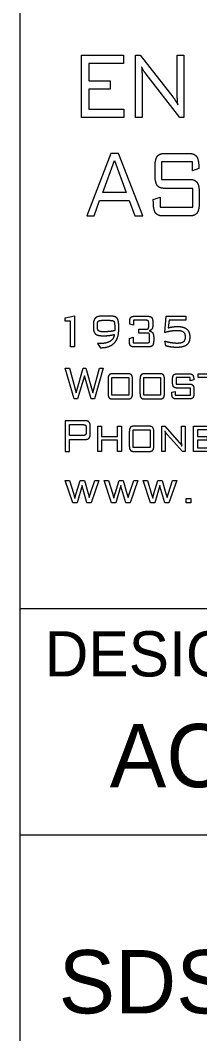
# Model space of a CAD drawing. Extents: x 0 to 34, y 0 to 22.
# Drawn here: x 32 to 32.397, y 2.06 to 4.301 of the extents above; entities that cross this region are included whole.
import ezdxf

# ---------------------------------------------------------------- set-up
doc = ezdxf.new("R2010")
doc.units = 0
for name, color, linetype in [('SH_Border', 7, 'Continuous'), ('SH_Data', 7, 'Continuous'), ('TX_X_20', 7, 'Continuous')]:
    doc.layers.add(name, color=color, linetype=linetype)

msp = doc.modelspace()

# ---------------------------------------------------------------- linework, layer by layer
at = {"layer": 'SH_Border'}
for p, q in [((32, 0.5), (32, 21.5)), ((32, 3), (33.5, 3)), ((32, 2.5), (33.5, 2.5))]:
    msp.add_line(p, q, dxfattribs=at)
at = {"layer": 'TX_X_20'}
for p, q in [((32.3205, 4.0065), (32.3719, 4.0065)), ((32.2979, 3.9618), (32.2979, 3.9738)), ((32.3958, 3.9164), (32.3958, 3.9009)), ((32.3733, 3.8681), (32.3169, 3.8681)), ((32.2009, 3.6465), (32.1793, 3.6465)), ((32.1811, 3.6374), (32.1977, 3.6374)), ((32.2536, 3.6465), (32.2812, 3.6465)), ((32.293, 3.6332), (32.293, 3.6271)), ((32.1618, 3.6299), (32.1618, 3.6208)), ((32.1705, 3.6225), (32.1705, 3.6269)), ((32.2087, 3.6145), (32.2087, 3.6145)), ((32.2177, 3.6166), (32.2177, 3.6256)), ((32.2841, 3.6257), (32.2841, 3.6297)), ((32.1708, 3.5861), (32.1763, 3.5771)), ((32.2861, 3.5939), (32.2861, 3.603)), ((32.295, 3.6002), (32.295, 3.5931)), ((32.3221, 3.5807), (32.3195, 3.5916)), ((32.2825, 3.5785), (32.2528, 3.5785)), ((32.2373, 3.5193), (32.205, 3.5193)), ((32.3079, 3.5193), (32.2756, 3.5193)), ((32.3476, 3.5193), (32.3725, 3.5193)), ((32.194, 3.506), (32.194, 3.4767)), ((32.2482, 3.4767), (32.2482, 3.506)), ((32.2647, 3.506), (32.2647, 3.4767)), ((32.3189, 3.4767), (32.3189, 3.506)), ((32.3367, 3.5008), (32.3367, 3.506)), ((32.384, 3.4834), (32.384, 3.4767)), ((32.205, 3.4635), (32.2373, 3.4635)), ((32.2756, 3.4635), (32.3079, 3.4635)), ((32.3731, 3.4635), (32.3459, 3.4635)), ((32.1457, 3.3995), (32.1457, 3.39)), ((32.1549, 3.3871), (32.1549, 3.4023)), ((32.2411, 3.39), (32.2411, 3.3607)), ((32.2844, 3.4033), (32.2521, 3.4033)), ((32.2954, 3.3607), (32.2954, 3.39)), ((32.32, 3.3921), (32.32, 3.3921)), ((32.2521, 3.3475), (32.2844, 3.3475))]:
    msp.add_line(p, q, dxfattribs=at)
for points in [[(32.1351, 4.0856), (32.1351, 4.224), (32.2283, 4.224), (32.2283, 4.2055), (32.1513, 4.2055), (32.1513, 4.167), (32.1984, 4.167), (32.1984, 4.1487), (32.1513, 4.1487), (32.1513, 4.1046), (32.2291, 4.1046), (32.2291, 4.0856)], [(32.1472, 3.8681), (32.1631, 3.8681), (32.1755, 3.9023), (32.241, 3.9023), (32.2534, 3.8681), (32.2712, 3.8681), (32.2174, 4.0065), (32.2001, 4.0065)], [(32.1823, 3.9199), (32.2083, 3.9907), (32.2344, 3.9199)], [(32.1114, 3.5785), (32.1114, 3.6358), (32.0995, 3.6358), (32.0995, 3.6426), (32.1197, 3.647), (32.1197, 3.5785)], [(32.1192, 3.4635), (32.0995, 3.5315), (32.1087, 3.5315), (32.1234, 3.4774), (32.1394, 3.5315), (32.145, 3.5315), (32.1605, 3.4774), (32.1754, 3.5315), (32.1835, 3.5315), (32.1638, 3.4635), (32.157, 3.4635), (32.142, 3.5149), (32.1264, 3.4635)], [(32.4228, 3.511), (32.4228, 3.4635), (32.4145, 3.4635), (32.4145, 3.511), (32.3934, 3.511), (32.3934, 3.5193), (32.444, 3.5193), (32.444, 3.511)], [(32.2024, 3.4719), (32.2024, 3.511), (32.2398, 3.511), (32.2398, 3.4719)], [(32.2731, 3.4719), (32.2731, 3.511), (32.3104, 3.511), (32.3104, 3.4719)], [(32.1712, 3.3475), (32.1712, 3.4031), (32.1796, 3.4031), (32.1796, 3.3808), (32.2153, 3.3808), (32.2153, 3.4031), (32.2237, 3.4031), (32.2237, 3.3475), (32.2153, 3.3475), (32.2153, 3.3723), (32.1796, 3.3723), (32.1796, 3.3475)], [(32.2496, 3.3559), (32.2496, 3.395), (32.2869, 3.395), (32.2869, 3.3559)], [(32.3831, 3.3475), (32.3831, 3.4033), (32.428, 3.4033), (32.428, 3.395), (32.3915, 3.395), (32.3915, 3.3807), (32.4135, 3.3807), (32.4135, 3.3723), (32.3915, 3.3723), (32.3915, 3.3556), (32.4285, 3.3556), (32.4285, 3.3475)], [(32.3667, 3.2341), (32.3667, 3.2436), (32.3771, 3.2436), (32.3771, 3.2341)]]:
    msp.add_lwpolyline(points, close=True, dxfattribs=at)
for points in [[(32.2695, 4.1672), (32.2695, 4.0856), (32.2547, 4.0856), (32.2547, 4.224), (32.2649, 4.224), (32.3374, 4.1315)], [(32.3469, 4.1481), (32.3469, 4.224), (32.3617, 4.224), (32.3617, 4.0856), (32.3526, 4.0856), (32.2782, 4.1819)], [(32.3947, 3.9762), (32.3947, 3.9733), (32.3808, 3.9676), (32.3808, 3.9877), (32.3124, 3.9877), (32.3124, 3.9491), (32.3733, 3.9491)], [(32.2942, 3.9009), (32.2942, 3.9047), (32.3092, 3.9096), (32.3092, 3.8874), (32.3813, 3.8874), (32.3813, 3.929), (32.3205, 3.929)], [(32.2792, 3.6374), (32.2501, 3.6374), (32.2501, 3.6269), (32.2419, 3.629), (32.2419, 3.6332)], [(32.3196, 3.6103), (32.3224, 3.6465), (32.3664, 3.6465), (32.3658, 3.6374), (32.3292, 3.6374), (32.3273, 3.6209)], [(32.2812, 3.6092), (32.262, 3.6092), (32.262, 3.6179), (32.2792, 3.6179)], [(32.2412, 3.5918), (32.2412, 3.5973), (32.2498, 3.5998), (32.2498, 3.5878), (32.2812, 3.5878)], [(32.3835, 3.507), (32.3835, 3.5057), (32.3758, 3.5036), (32.3758, 3.511), (32.3444, 3.511), (32.3444, 3.4965), (32.3731, 3.4965)], [(32.335, 3.4767), (32.335, 3.4782), (32.3427, 3.4802), (32.3427, 3.4719), (32.3764, 3.4719), (32.3764, 3.4876), (32.3476, 3.4876)], [(32.1433, 3.4155), (32.0995, 3.4155), (32.0995, 3.3475), (32.1086, 3.3475), (32.1086, 3.374), (32.1433, 3.374)], [(32.1398, 3.3829), (32.1086, 3.3829), (32.1086, 3.4067), (32.1398, 3.4067)], [(32.3206, 3.3821), (32.3206, 3.3475), (32.3129, 3.3475), (32.3129, 3.4033), (32.3193, 3.4033), (32.3521, 3.3668)], [(32.3567, 3.3696), (32.3567, 3.4033), (32.3645, 3.4033), (32.3645, 3.3475), (32.3587, 3.3475), (32.3253, 3.3844)], [(32.1237, 3.2545), (32.1323, 3.2834), (32.1418, 3.2834), (32.1499, 3.2548), (32.1525, 3.2454), (32.1556, 3.2549), (32.165, 3.2834), (32.1739, 3.2834), (32.1569, 3.2341), (32.1474, 3.2341), (32.1388, 3.2636), (32.1367, 3.272), (32.1256, 3.2341), (32.1161, 3.2341), (32.0995, 3.2834), (32.109, 3.2834), (32.1177, 3.2549), (32.1208, 3.2443)], [(32.2096, 3.2545), (32.2183, 3.2834), (32.2277, 3.2834), (32.2358, 3.2548), (32.2385, 3.2454), (32.2416, 3.2549), (32.2509, 3.2834), (32.2599, 3.2834), (32.2429, 3.2341), (32.2334, 3.2341), (32.2248, 3.2636), (32.2226, 3.272), (32.2116, 3.2341), (32.202, 3.2341), (32.1855, 3.2834), (32.195, 3.2834), (32.2037, 3.2549), (32.2068, 3.2443)], [(32.2956, 3.2545), (32.3042, 3.2834), (32.3137, 3.2834), (32.3218, 3.2548), (32.3245, 3.2454), (32.3276, 3.2549), (32.3369, 3.2834), (32.3459, 3.2834), (32.3288, 3.2341), (32.3193, 3.2341), (32.3108, 3.2636), (32.3086, 3.272), (32.2976, 3.2341), (32.288, 3.2341), (32.2715, 3.2834), (32.281, 3.2834), (32.2896, 3.2549), (32.2928, 3.2443)]]:
    msp.add_lwpolyline(points, dxfattribs=at)
for points in [[(32.2766, 4.184), (32.2711, 4.191), (32.2684, 4.1975)], [(32.2684, 4.1975), (32.269, 4.1912), (32.2692, 4.184)], [(32.2692, 4.184), (32.2695, 4.1769), (32.2695, 4.1672)], [(32.2782, 4.1819), (32.2777, 4.1825), (32.2766, 4.184)], [(32.3473, 4.128), (32.3469, 4.1353), (32.3469, 4.1481)], [(32.3374, 4.1315), (32.3398, 4.1283), (32.3426, 4.1239)], [(32.3426, 4.1239), (32.3454, 4.1194), (32.3484, 4.114)], [(32.3484, 4.114), (32.3476, 4.1207), (32.3473, 4.128)], [(32.2979, 3.9738), (32.2979, 3.9928), (32.3026, 3.9997)], [(32.3026, 3.9997), (32.3072, 4.0065), (32.3205, 4.0065)], [(32.3719, 4.0065), (32.3849, 4.0065), (32.3898, 3.9998)], [(32.3898, 3.9998), (32.3947, 3.9931), (32.3947, 3.9762)], [(32.3026, 3.9359), (32.2979, 3.9428), (32.2979, 3.9618)], [(32.3733, 3.9491), (32.3863, 3.9491), (32.391, 3.9423)], [(32.3205, 3.929), (32.3072, 3.929), (32.3026, 3.9359)], [(32.391, 3.9423), (32.3958, 3.9355), (32.3958, 3.9164)], [(32.2989, 3.875), (32.2942, 3.8819), (32.2942, 3.9009)], [(32.3958, 3.9009), (32.3958, 3.8818), (32.3911, 3.875)], [(32.3169, 3.8681), (32.3037, 3.8681), (32.2989, 3.875)], [(32.3911, 3.875), (32.3865, 3.8681), (32.3733, 3.8681)], [(32.1661, 3.6425), (32.1618, 3.6384), (32.1618, 3.6299)], [(32.1793, 3.6465), (32.1703, 3.6465), (32.1661, 3.6425)], [(32.1705, 3.6269), (32.1705, 3.6331), (32.1726, 3.6353)], [(32.1726, 3.6353), (32.1748, 3.6374), (32.1811, 3.6374)], [(32.1977, 3.6374), (32.2056, 3.6374), (32.2073, 3.6349)], [(32.2141, 3.6421), (32.2105, 3.6465), (32.2009, 3.6465)], [(32.2073, 3.6349), (32.209, 3.6325), (32.209, 3.6187)], [(32.2177, 3.6256), (32.2177, 3.6376), (32.2141, 3.6421)], [(32.2419, 3.6332), (32.2419, 3.6409), (32.2443, 3.6437)], [(32.2443, 3.6437), (32.2467, 3.6465), (32.2536, 3.6465)], [(32.2832, 3.6359), (32.2822, 3.6374), (32.2792, 3.6374)], [(32.2812, 3.6465), (32.2882, 3.6465), (32.2906, 3.6437)], [(32.2841, 3.6297), (32.2841, 3.6345), (32.2832, 3.6359)], [(32.2906, 3.6437), (32.293, 3.6409), (32.293, 3.6332)], [(32.1618, 3.6208), (32.1618, 3.6109), (32.1665, 3.6071)], [(32.1731, 3.6142), (32.1705, 3.6164), (32.1705, 3.6225)], [(32.1833, 3.612), (32.1758, 3.612), (32.1731, 3.6142)], [(32.1966, 3.6126), (32.1902, 3.612), (32.1833, 3.612)], [(32.2087, 3.6145), (32.203, 3.6133), (32.1966, 3.6126)], [(32.2079, 3.5873), (32.2177, 3.5976), (32.2177, 3.6166)], [(32.209, 3.6168), (32.2089, 3.6157), (32.2087, 3.6145)], [(32.209, 3.6187), (32.209, 3.6179), (32.209, 3.6168)], [(32.2792, 3.6179), (32.2822, 3.6179), (32.2832, 3.6194)], [(32.2851, 3.608), (32.2842, 3.6092), (32.2812, 3.6092)], [(32.2832, 3.6194), (32.2841, 3.6209), (32.2841, 3.6257)], [(32.2911, 3.6183), (32.2892, 3.6154), (32.2847, 3.6141)], [(32.2847, 3.6141), (32.2902, 3.6131), (32.2926, 3.6098)], [(32.2861, 3.603), (32.2861, 3.6068), (32.2851, 3.608)], [(32.293, 3.6271), (32.293, 3.6212), (32.2911, 3.6183)], [(32.2926, 3.6098), (32.295, 3.6066), (32.295, 3.6002)], [(32.3335, 3.6134), (32.3269, 3.6124), (32.3196, 3.6103)], [(32.3273, 3.6209), (32.3324, 3.6223), (32.3374, 3.623)], [(32.3463, 3.6145), (32.3402, 3.6145), (32.3335, 3.6134)], [(32.3374, 3.623), (32.3425, 3.6237), (32.3475, 3.6237)], [(32.3609, 3.6112), (32.3563, 3.6145), (32.3463, 3.6145)], [(32.3475, 3.6237), (32.3614, 3.6237), (32.3681, 3.618)], [(32.3654, 3.6005), (32.3654, 3.6079), (32.3609, 3.6112)], [(32.3681, 3.618), (32.3748, 3.6123), (32.3748, 3.6004)], [(32.1665, 3.6071), (32.1712, 3.6032), (32.1838, 3.6032)], [(32.1713, 3.5861), (32.171, 3.5861), (32.1708, 3.5861)], [(32.174, 3.5859), (32.1732, 3.5859), (32.1713, 3.5861)], [(32.1985, 3.5909), (32.1901, 3.5859), (32.174, 3.5859)], [(32.18, 3.5769), (32.198, 3.5769), (32.2079, 3.5873)], [(32.1838, 3.6032), (32.19, 3.6032), (32.1961, 3.6039)], [(32.1961, 3.6039), (32.2021, 3.6047), (32.208, 3.6061)], [(32.208, 3.6061), (32.2068, 3.5958), (32.1985, 3.5909)], [(32.2436, 3.5813), (32.2412, 3.5841), (32.2412, 3.5918)], [(32.2812, 3.5878), (32.2842, 3.5878), (32.2852, 3.589)], [(32.2852, 3.589), (32.2861, 3.5902), (32.2861, 3.5939)], [(32.295, 3.5931), (32.295, 3.5847), (32.2922, 3.5816)], [(32.3195, 3.5916), (32.3269, 3.5894), (32.3339, 3.5883)], [(32.3339, 3.5883), (32.3409, 3.5872), (32.3469, 3.5872)], [(32.3469, 3.5872), (32.3568, 3.5872), (32.3611, 3.5903)], [(32.3611, 3.5903), (32.3654, 3.5935), (32.3654, 3.6005)], [(32.3748, 3.6004), (32.3748, 3.5882), (32.3679, 3.5829)], [(32.1763, 3.5771), (32.177, 3.577), (32.1778, 3.5769)], [(32.1778, 3.5769), (32.1785, 3.5769), (32.18, 3.5769)], [(32.2528, 3.5785), (32.246, 3.5785), (32.2436, 3.5813)], [(32.2922, 3.5816), (32.2895, 3.5785), (32.2825, 3.5785)], [(32.3348, 3.5782), (32.3292, 3.579), (32.3221, 3.5807)], [(32.3454, 3.5775), (32.3404, 3.5775), (32.3348, 3.5782)], [(32.3679, 3.5829), (32.3611, 3.5775), (32.3454, 3.5775)], [(32.205, 3.5193), (32.1986, 3.5193), (32.1963, 3.5165)], [(32.2459, 3.5165), (32.2436, 3.5193), (32.2373, 3.5193)], [(32.2756, 3.5193), (32.2693, 3.5193), (32.267, 3.5165)], [(32.3165, 3.5165), (32.3142, 3.5193), (32.3079, 3.5193)], [(32.339, 3.5165), (32.3413, 3.5193), (32.3476, 3.5193)], [(32.3725, 3.5193), (32.3787, 3.5193), (32.3811, 3.5166)], [(32.1963, 3.5165), (32.194, 3.5137), (32.194, 3.506)], [(32.2482, 3.506), (32.2482, 3.5137), (32.2459, 3.5165)], [(32.267, 3.5165), (32.2647, 3.5137), (32.2647, 3.506)], [(32.3189, 3.506), (32.3189, 3.5137), (32.3165, 3.5165)], [(32.3367, 3.506), (32.3367, 3.5137), (32.339, 3.5165)], [(32.339, 3.4903), (32.3367, 3.4931), (32.3367, 3.5008)], [(32.3731, 3.4965), (32.3794, 3.4965), (32.3817, 3.4938)], [(32.3811, 3.5166), (32.3835, 3.5139), (32.3835, 3.507)], [(32.194, 3.4767), (32.194, 3.4689), (32.1963, 3.4662)], [(32.2459, 3.4662), (32.2482, 3.469), (32.2482, 3.4767)], [(32.2647, 3.4767), (32.2647, 3.4689), (32.2669, 3.4662)], [(32.3166, 3.4662), (32.3189, 3.469), (32.3189, 3.4767)], [(32.3372, 3.4662), (32.335, 3.4689), (32.335, 3.4767)], [(32.3476, 3.4876), (32.3413, 3.4876), (32.339, 3.4903)], [(32.3817, 3.4938), (32.384, 3.4911), (32.384, 3.4834)], [(32.384, 3.4767), (32.384, 3.4689), (32.3817, 3.4662)], [(32.1963, 3.4662), (32.1985, 3.4635), (32.205, 3.4635)], [(32.2373, 3.4635), (32.2437, 3.4635), (32.2459, 3.4662)], [(32.2669, 3.4662), (32.2692, 3.4635), (32.2756, 3.4635)], [(32.3079, 3.4635), (32.3143, 3.4635), (32.3166, 3.4662)], [(32.3459, 3.4635), (32.3395, 3.4635), (32.3372, 3.4662)], [(32.3817, 3.4662), (32.3795, 3.4635), (32.3731, 3.4635)], [(32.1398, 3.4067), (32.1431, 3.4067), (32.1444, 3.4051)], [(32.1522, 3.4124), (32.1495, 3.4155), (32.1433, 3.4155)], [(32.1549, 3.4023), (32.1549, 3.4093), (32.1522, 3.4124)], [(32.1444, 3.3845), (32.1431, 3.3829), (32.1398, 3.3829)], [(32.1444, 3.4051), (32.1457, 3.4035), (32.1457, 3.3995)], [(32.1457, 3.39), (32.1457, 3.3861), (32.1444, 3.3845)], [(32.1522, 3.3771), (32.1549, 3.3802), (32.1549, 3.3871)], [(32.2435, 3.4005), (32.2411, 3.3977), (32.2411, 3.39)], [(32.2521, 3.4033), (32.2458, 3.4033), (32.2435, 3.4005)], [(32.293, 3.4005), (32.2907, 3.4033), (32.2844, 3.4033)], [(32.2954, 3.39), (32.2954, 3.3977), (32.293, 3.4005)], [(32.32, 3.3921), (32.3203, 3.3896), (32.3205, 3.3871)], [(32.3223, 3.3883), (32.321, 3.3902), (32.32, 3.3921)], [(32.3205, 3.3871), (32.3206, 3.3846), (32.3206, 3.3821)], [(32.3253, 3.3844), (32.3235, 3.3865), (32.3223, 3.3883)], [(32.1433, 3.374), (32.1495, 3.374), (32.1522, 3.3771)], [(32.3521, 3.3668), (32.3535, 3.3653), (32.3548, 3.3634)], [(32.3548, 3.3634), (32.3561, 3.3615), (32.3574, 3.3592)], [(32.3569, 3.3642), (32.3567, 3.3668), (32.3567, 3.3696)], [(32.3574, 3.3592), (32.3571, 3.3617), (32.3569, 3.3642)], [(32.2411, 3.3607), (32.2411, 3.3529), (32.2434, 3.3502)], [(32.2434, 3.3502), (32.2457, 3.3475), (32.2521, 3.3475)], [(32.2844, 3.3475), (32.2908, 3.3475), (32.2931, 3.3502)], [(32.2931, 3.3502), (32.2954, 3.353), (32.2954, 3.3607)], [(32.1208, 3.2443), (32.121, 3.2451), (32.1237, 3.2545)], [(32.2068, 3.2443), (32.207, 3.2451), (32.2096, 3.2545)], [(32.2928, 3.2443), (32.293, 3.2451), (32.2956, 3.2545)]]:
    msp.add_open_spline(points, degree=2, dxfattribs=at)

# ---------------------------------------------------------------- texts
at = {"layer": 'SH_Data'}
for s, height, p in [('DESIGNER', 0.1, (32.054, 2.85)), ('ACB', 0.14, (32.1979, 2.605)), ('SDS', 0.14, (32.0848, 2.105))]:
    msp.add_text(s, height=height, dxfattribs=at).set_placement(p)

doc.saveas('drawing.dxf')
